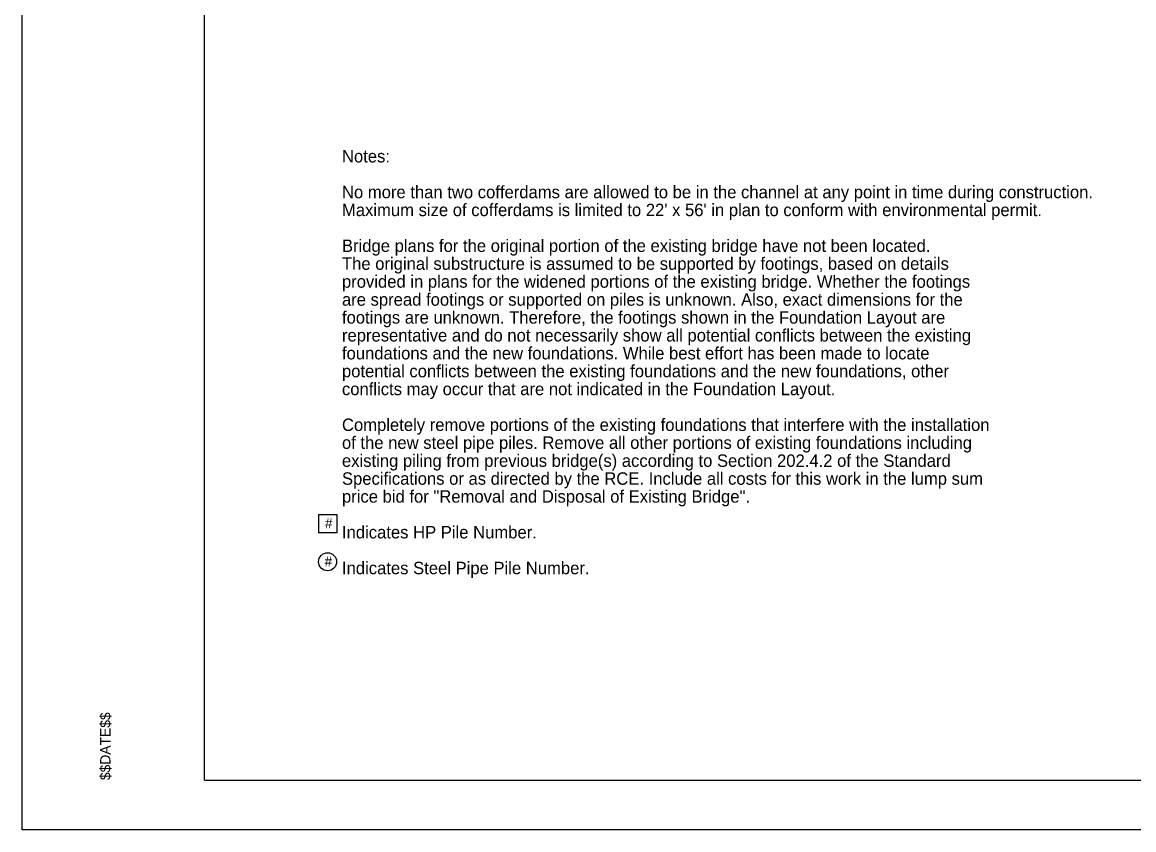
# Model space of a CAD drawing. Extents: x -10371 to -10009, y 1939 to 2167.
# Drawn here: x -10370.6 to -10258.8, y 1939.5 to 2020.7 of the extents above; entities that cross this region are included whole.
import ezdxf

# ---------------------------------------------------------------- set-up
doc = ezdxf.new("R2010")
doc.units = 0
for name, color, linetype in [('BR_BORDER LINES', 7, 'Continuous'), ('BR_TEXT', 7, 'Continuous'), ('RD_SHT_IplotShp', 7, 'Continuous')]:
    doc.layers.add(name, color=color, linetype=linetype)

msp = doc.modelspace()

# ---------------------------------------------------------------- linework, layer by layer
at = {"layer": 'BR_BORDER LINES'}
for q in [(-10352.25, 2154.49), (-10015.58, 1944.49)]:
    msp.add_line((-10352.25, 1944.49), q, dxfattribs=at)
at = {"layer": 'BR_TEXT'}
for p, q in [((-10340.77, 1971.2), (-10340.77, 1969.38)), ((-10340.77, 1971.2), (-10338.95, 1971.2)), ((-10338.95, 1971.2), (-10338.95, 1969.38)), ((-10338.95, 1969.38), (-10340.77, 1969.38))]:
    msp.add_line(p, q, dxfattribs=at)
msp.add_circle((-10339.87, 1966.45), 0.91, dxfattribs=at)
at = {"layer": 'RD_SHT_IplotShp'}
msp.add_lwpolyline([(-10370.58, 2159.49), (-10010.58, 2159.49), (-10010.58, 1939.49), (-10370.58, 1939.49)], close=True, dxfattribs=at)

# ---------------------------------------------------------------- texts
at = {"layer": 'BR_TEXT'}
for s, height, p in [('Notes:', 1.25, (-10338.42, 2006.62)), ('No more than two cofferdams are allowed to be in the channel at any point in time during construction.', 1.25, (-10338.42, 2003.02)), ("Maximum size of cofferdams is limited to 22' x 56' in plan to conform with environmental permit.", 1.25, (-10338.42, 2001.22)), ('Bridge plans for the original portion of the existing bridge have not been located. ', 1.25, (-10338.42, 1997.62)), ('The original substructure is assumed to be supported by footings, based on details ', 1.25, (-10338.42, 1995.82)), ('provided in plans for the widened portions of the existing bridge. Whether the footings ', 1.25, (-10338.42, 1994.02)), ('are spread footings or supported on piles is unknown. Also, exact dimensions for the ', 1.25, (-10338.42, 1992.21)), ('footings are unknown. Therefore, the footings shown in the Foundation Layout are ', 1.25, (-10338.42, 1990.41)), ('representative and do not necessarily show all potential conflicts between the existing ', 1.25, (-10338.42, 1988.61)), ('foundations and the new foundations. While best effort has been made to locate ', 1.25, (-10338.42, 1986.81)), ('potential conflicts between the existing foundations and the new foundations, other ', 1.25, (-10338.42, 1985.01)), ('conflicts may occur that are not indicated in the Foundation Layout.', 1.25, (-10338.42, 1983.21)), ('Completely remove portions of the existing foundations that interfere with the installation ', 1.25, (-10338.42, 1979.61)), ('of the new steel pipe piles. Remove all other portions of existing foundations including ', 1.25, (-10338.42, 1977.81)), ('existing piling from previous bridge(s) according to Section 202.4.2 of the Standard ', 1.25, (-10338.42, 1976)), ('Specifications or as directed by the RCE. Include all costs for this work in the lump sum ', 1.25, (-10338.42, 1974.2)), ('price bid for "Removal and Disposal of Existing Bridge".', 1.25, (-10338.42, 1972.4)), ('#', 1, (-10340.12, 1969.82)), ('Indicates HP Pile Number.', 1.25, (-10338.42, 1968.8)), ('#', 1, (-10340.16, 1965.98)), ('Indicates Steel Pipe Pile Number.', 1.25, (-10338.42, 1965.2))]:
    msp.add_text(s, height=height, dxfattribs=at).set_placement(p)
msp.add_text('$$DATE$$', height=1.042, rotation=90, dxfattribs=at).set_placement((-10361.7, 1944.49))

doc.saveas('drawing.dxf')
